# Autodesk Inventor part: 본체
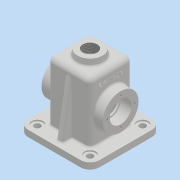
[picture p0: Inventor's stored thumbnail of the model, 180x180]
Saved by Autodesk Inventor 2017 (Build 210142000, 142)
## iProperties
Part Number: 본체
Material: 일반
Document SubType Name: Modeling
Designer: MRC
Density: 1 g/cm^3
Appearance: 기본값
Author: MRC
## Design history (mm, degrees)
sketch "스케치1"
  geometry: L1 (-57, -57)-(57, -57); L2 (57, -57)-(57, 57); L3 (57, 57)-(-57, 57); L4 (-57, 57)-(-57, -57); L5 (-57, -57)-(57, 57); L6 (57, -57)-(-57, 57); 1 further point
  constraints: 12 end point, 2 midpoint, 2 parallel, 1 horizontal, 1 perpendicular
  dimensions: "d0" = 114 distance of L3.end L2.end; "d1" = 114 distance of L2.end L1.end
extrude "돌출1" new body sketch "스케치1" distance "d2" = 10; taper "d3" = 0 deg
sketch "스케치2"
  geometry: L1 (-34, -34)-(34, -34); L2 (34, -34)-(34, 34); L3 (34, 34)-(-34, 34); L4 (-34, 34)-(-34, -34); L5 (-34, -34)-(34, 34); L6 (34, -34)-(-34, 34); 1 further point
  constraints: 12 end point, 2 midpoint, 2 parallel, 1 horizontal, 1 perpendicular
  dimensions: "d4" = 68 distance of L3.end L2.end; "d5" = 68 distance of L2.end L1.end
extrude "돌출2" join sketch "스케치2" distance "d6" = 95; taper "d7" = 0 deg
feature "쉘1" dims "d10" = 10, "d11" = 5
sketch "스케치4"
  geometry: L1 (-10, 91)-(-10, -23) reference; C1 r 28.5 at (42, 34); 2 further points
  constraints: 1 centre point, 1 horizontal alignment, 1 midpoint
  dimensions: "d12" = 57 diameter of C1; "d13" = 52 distance from line of L1 C1.centre
extrude "돌출3" join sketch "스케치4" distance "d14" = 15; taper "d15" = 0 deg
hole "구멍1" diameter "d18" = 30; stored, may be unused: countersink angle "d22" = 90 deg, drill point angle "d24" = 118 deg; dims "d16" = 10, "d17" = 10, "d19" = 6, "d20" = 35, "d21" = 17, "d23" = 40
sketch "스케치5"
  geometry: C1 r 17.5 at (0, 0) reference; 2 further points
  constraints: 1 horizontal alignment
  dimensions: "d25" = 22 distance of C1.centre point (22, 0)
hole "구멍2" sketch "스케치5" at (22, 0) diameter "d26" = 3.242; stored, may be unused: countersink angle "d30" = 90 deg, drill point angle "d32" = 118 deg; dims "d27" = 8, "d28" = 35, "d29" = 17, "d31" = 10
node "작업 평면1"
sketch "스케치6"
  geometry: C1 r 20 at (0, 0); 1 further point
  constraints: 1 centre point, 1 coincident
  dimensions: "d37" = 40 diameter of C1
extrude "돌출4" join sketch "스케치6" stored distance "d38" = 10; taper "d39" = 8 deg
hole "구멍3" diameter "d42" = 22.835; stored, may be unused: countersink angle "d46" = 90 deg, drill point angle "d48" = 118 deg; dims "d40" = 10, "d41" = 10, "d43" = 40, "d44" = 35, "d45" = 17, "d47" = 40
sketch "스케치7"
  geometry: L1 (-34, 95.069)-(-49, 10); L2 (-57, 10)-(57, 10) reference; L3 (-34, 10)-(-34, 105) reference; L4 (-57, 0)-(-57, 10) reference; 1 further point
  constraints: 2 end point, 2 point on line
  dimensions: "d49" = 8 distance from line of L4 L1.end; "d50" = 10 deg angle of L4 L1
feature "리브1" sketch "스케치7" dims "d51" = 1, "d52" = 10, "d53" = 0, "d54" = 0, "d55" = 1, "d56" = 1
fillet "모깎기3" dims "d57" = 15
sketch "스케치8"
  geometry: A1 r 15 centre (42, 42) between (57, 42) and (42, 57) reference; A2 r 15 centre (-42, 42) between (-42, 57) and (-57, 42) reference; A3 r 15 centre (-42, -42) between (-57, -42) and (-42, -57) reference; A4 r 15 centre (42, -42) between (42, -57) and (57, -42) reference; 1 further point
hole "구멍4" sketch "스케치8" at (-42, 42), (-42, -42), (42, 42), (42, -42) diameter "d58" = 10; stored, may be unused: countersink angle "d62" = 90 deg, drill point angle "d64" = 118 deg; dims "d59" = 10, "d60" = 18, "d61" = 2, "d63" = 20
fillet "모깎기4" dims "d65" = 8
fillet "모깎기5" dims "d66" = 8
fillet "모깎기6" dims "d67" = 3
fillet "모깎기7" dims "d68" = 3
fillet "모깎기8" dims "d69" = 3
fillet "모깎기9" dims "d70" = 3
fillet "모깎기10" dims "d71" = 0.3
sketch "스케치9"
  geometry: L1 (0, -8)-(84, -8) reference; L2 (-18, 6)-(-18, 46) reference; 2 further points
  constraints: 1 other
  dimensions: "d72" = 34 distance from line of L1 point (7, 26); "d73" = 25 distance from line of point (7, 26) L2
feature "엠보싱1" sketch "스케치9" dims "d0" = 114, "d1" = 114, "d74" = 0.5, "d75" = 0
node "솔리드1"
pattern_circular "원형 패턴1" dims angle "d34" = 360 deg
mirror "미러1"
mirror "미러2"
